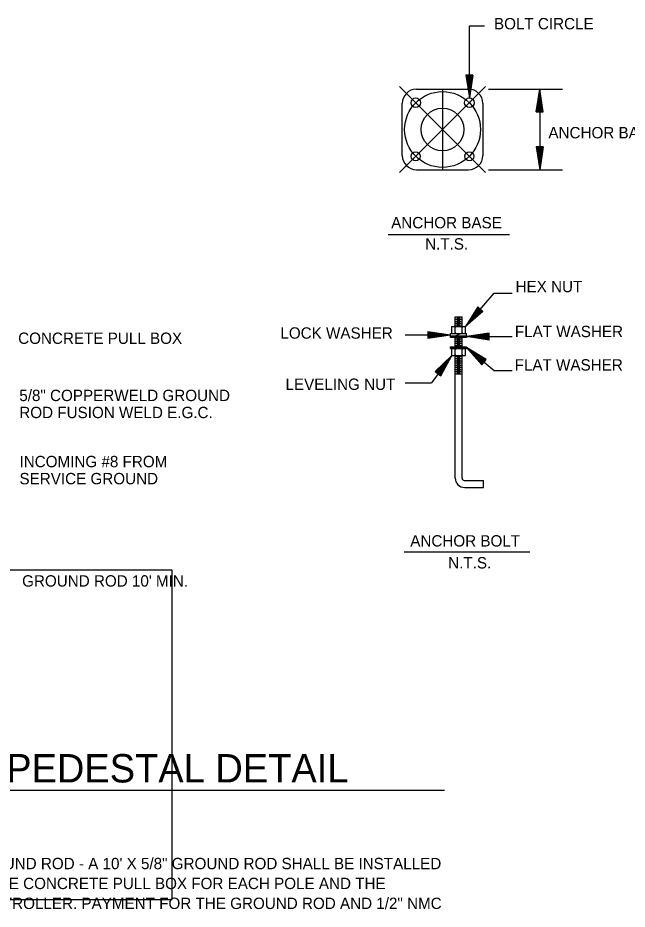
# Model space of a CAD drawing. Extents: x 418532 to 420296, y -565948 to -565286.
# Drawn here: x 419153.1 to 419394.2, y -565645.2 to -565292.4 of the extents above; entities that cross this region are included whole.
import ezdxf

# ---------------------------------------------------------------- set-up
doc = ezdxf.new("R2010")
doc.units = 0
doc.layers.add('R_Draft', color=7, linetype='Continuous')
doc.layers.add('Template', color=7, linetype='Continuous')

msp = doc.modelspace()

# ---------------------------------------------------------------- linework, layer by layer
at = {"layer": 'R_Draft'}
for p, q in [((419331.76, -565324.13), (419331.76, -565295.53)), ((419331.76, -565295.53), (419337.79, -565295.53)), ((419330.41, -565315.13), (419331.76, -565324.13)), ((419333.11, -565315.13), (419330.41, -565315.13)), ((419330.63, -565315.13), (419331.76, -565322.62)), ((419330.86, -565315.13), (419331.76, -565321.07)), ((419331.09, -565315.13), (419331.76, -565319.58)), ((419331.32, -565315.13), (419331.76, -565318.05)), ((419331.55, -565315.13), (419331.76, -565316.55)), ((419333.11, -565315.13), (419331.76, -565324.13)), ((419332.19, -565315.13), (419331.76, -565318.05)), ((419332.65, -565315.13), (419331.76, -565321.07)), ((419332.88, -565315.13), (419331.76, -565322.62)), ((419332.43, -565315.13), (419331.76, -565319.58)), ((419331.97, -565315.13), (419331.76, -565316.55)), ((419338.12, -565353.58), (419304.18, -565319.64)), ((419304.18, -565353.58), (419338.12, -565319.64)), ((419310.84, -565320.67), (419331.46, -565320.67)), ((419321.15, -565320.67), (419321.15, -565352.54)), ((419339.34, -565320.67), (419368.59, -565320.67)), ((419358.24, -565329.67), (419359.59, -565320.67)), ((419358.46, -565329.67), (419359.59, -565322.17)), ((419359.59, -565320.67), (419359.59, -565352.54)), ((419360.94, -565329.67), (419359.59, -565320.67)), ((419360.71, -565329.67), (419359.59, -565322.17)), ((419305.21, -565346.92), (419305.21, -565326.29)), ((419337.09, -565326.29), (419337.09, -565346.92)), ((419358.69, -565329.67), (419359.59, -565323.72)), ((419358.92, -565329.67), (419359.59, -565325.22)), ((419359.15, -565329.67), (419359.59, -565326.74)), ((419360.48, -565329.67), (419359.59, -565323.72)), ((419360.26, -565329.67), (419359.59, -565325.22)), ((419360.03, -565329.67), (419359.59, -565326.74)), ((419358.24, -565329.67), (419360.94, -565329.67)), ((419359.38, -565329.67), (419359.59, -565328.25)), ((419359.8, -565329.67), (419359.59, -565328.25)), ((419358.24, -565343.54), (419359.59, -565352.54)), ((419360.94, -565343.54), (419358.24, -565343.54)), ((419358.46, -565343.54), (419359.59, -565351.04)), ((419358.69, -565343.54), (419359.59, -565349.49)), ((419358.92, -565343.54), (419359.59, -565348)), ((419359.15, -565343.54), (419359.59, -565346.47)), ((419359.38, -565343.54), (419359.59, -565344.97)), ((419360.94, -565343.54), (419359.59, -565352.54)), ((419360.02, -565343.54), (419359.59, -565346.47)), ((419360.48, -565343.54), (419359.59, -565349.49)), ((419360.71, -565343.54), (419359.59, -565351.04)), ((419360.26, -565343.54), (419359.59, -565348)), ((419359.8, -565343.54), (419359.59, -565344.97)), ((419310.84, -565352.54), (419331.46, -565352.54)), ((419339.34, -565352.54), (419368.59, -565352.54)), ((419347.68, -565378.35), (419299.59, -565378.35)), ((419330.21, -565414.57), (419341.63, -565401.41)), ((419341.63, -565401.41), (419348.66, -565401.41)), ((419335.06, -565406.87), (419330.21, -565414.57)), ((419335.23, -565407.02), (419331.19, -565413.43)), ((419335.41, -565407.17), (419332.2, -565412.26)), ((419335.58, -565407.31), (419333.18, -565411.12)), ((419335.75, -565407.46), (419334.18, -565409.97)), ((419336.42, -565408.04), (419334.18, -565409.97)), ((419337.11, -565408.63), (419335.06, -565406.87)), ((419335.93, -565407.61), (419335.16, -565408.83)), ((419336.25, -565407.89), (419335.16, -565408.83)), ((419326.16, -565410.82), (419328.86, -565410.82)), ((419326.16, -565414.57), (419326.16, -565410.82)), ((419326.84, -565411.27), (419328.19, -565411.27)), ((419328.86, -565414.57), (419328.86, -565410.82)), ((419337.11, -565408.63), (419330.21, -565414.57)), ((419336.94, -565408.49), (419331.19, -565413.43)), ((419336.77, -565408.34), (419332.2, -565412.26)), ((419336.59, -565408.19), (419333.18, -565411.12)), ((419324.81, -565417.41), (419324.81, -565414.57)), ((419324.81, -565414.57), (419330.21, -565414.57)), ((419326.16, -565411.68), (419328.86, -565411.68)), ((419326.16, -565412.55), (419328.86, -565412.55)), ((419326.16, -565413.41), (419328.86, -565413.41)), ((419326.16, -565414.28), (419328.86, -565414.28)), ((419326.16, -565417.41), (419326.16, -565414.57)), ((419326.84, -565412.13), (419328.19, -565412.13)), ((419326.84, -565413), (419328.19, -565413)), ((419326.84, -565413.86), (419328.19, -565413.86)), ((419328.86, -565417.41), (419328.86, -565414.57)), ((419330.21, -565417.41), (419330.21, -565414.57)), ((419306.36, -565417.86), (419324.36, -565417.86)), ((419315.36, -565416.51), (419324.36, -565417.86)), ((419315.36, -565416.51), (419315.36, -565419.21)), ((419315.36, -565416.74), (419322.86, -565417.86)), ((419315.36, -565416.97), (419321.31, -565417.86)), ((419315.36, -565417.19), (419319.81, -565417.86)), ((419315.36, -565417.43), (419318.29, -565417.86)), ((419315.36, -565417.65), (419316.78, -565417.86)), ((419315.36, -565419.21), (419324.36, -565417.86)), ((419315.36, -565418.3), (419318.29, -565417.86)), ((419315.36, -565418.76), (419321.31, -565417.86)), ((419315.36, -565418.99), (419322.86, -565417.86)), ((419315.36, -565418.53), (419319.81, -565417.86)), ((419315.36, -565418.07), (419316.78, -565417.86)), ((419324.36, -565418.91), (419324.36, -565417.41)), ((419324.36, -565417.41), (419330.66, -565417.41)), ((419324.36, -565418.31), (419330.66, -565418.31)), ((419324.36, -565418.88), (419324.93, -565418.31)), ((419324.36, -565418.57), (419324.61, -565418.31)), ((419324.65, -565418.91), (419325.25, -565418.31)), ((419324.97, -565418.91), (419325.57, -565418.31)), ((419325.28, -565418.91), (419325.88, -565418.31)), ((419325.6, -565418.91), (419326.2, -565418.31)), ((419325.92, -565418.91), (419326.52, -565418.31)), ((419326.17, -565418.32), (419328.14, -565417.44)), ((419326.24, -565418.91), (419326.84, -565418.31)), ((419326.56, -565418.91), (419327.16, -565418.31)), ((419326.88, -565418.91), (419327.48, -565418.31)), ((419327.19, -565418.91), (419327.79, -565418.31)), ((419327.51, -565418.91), (419328.11, -565418.31)), ((419327.83, -565418.91), (419328.43, -565418.31)), ((419328.15, -565418.91), (419328.75, -565418.31)), ((419328.47, -565418.91), (419329.07, -565418.31)), ((419328.78, -565418.91), (419329.38, -565418.31)), ((419329.1, -565418.91), (419329.7, -565418.31)), ((419329.42, -565418.91), (419330.02, -565418.31)), ((419329.74, -565418.91), (419330.34, -565418.31)), ((419330.06, -565418.91), (419330.66, -565418.31)), ((419330.38, -565418.91), (419330.66, -565418.63)), ((419339.66, -565417.26), (419330.66, -565418.61)), ((419330.66, -565418.91), (419330.66, -565417.41)), ((419330.66, -565418.61), (419348.66, -565418.61)), ((419339.66, -565419.96), (419330.66, -565418.61)), ((419339.66, -565417.49), (419332.16, -565418.61)), ((419339.66, -565419.74), (419332.16, -565418.61)), ((419339.66, -565417.72), (419333.71, -565418.61)), ((419339.66, -565419.51), (419333.71, -565418.61)), ((419339.66, -565417.94), (419335.21, -565418.61)), ((419339.66, -565419.29), (419335.21, -565418.61)), ((419339.66, -565418.17), (419336.74, -565418.61)), ((419339.66, -565419.05), (419336.74, -565418.61)), ((419339.66, -565418.4), (419338.24, -565418.61)), ((419339.66, -565418.83), (419338.24, -565418.61)), ((419339.66, -565419.96), (419339.66, -565417.26)), ((419330.66, -565418.91), (419324.36, -565418.91)), ((419326.16, -565422.66), (419326.16, -565418.91)), ((419326.16, -565419.47), (419328.86, -565419.47)), ((419326.16, -565420.34), (419328.86, -565420.34)), ((419326.16, -565421.2), (419328.86, -565421.2)), ((419326.16, -565422.07), (419328.86, -565422.07)), ((419326.84, -565419.06), (419328.19, -565419.06)), ((419326.84, -565419.92), (419328.19, -565419.92)), ((419326.84, -565420.79), (419328.19, -565420.79)), ((419326.84, -565421.65), (419328.19, -565421.65)), ((419328.86, -565422.66), (419328.86, -565418.91)), ((419324.36, -565423.26), (419324.36, -565422.66)), ((419324.36, -565422.66), (419330.66, -565422.66)), ((419324.36, -565422.97), (419324.66, -565422.66)), ((419324.36, -565423.26), (419330.66, -565423.26)), ((419324.38, -565423.26), (419324.98, -565422.66)), ((419324.7, -565423.26), (419325.3, -565422.66)), ((419324.81, -565426.11), (419324.81, -565423.26)), ((419325.02, -565423.26), (419325.62, -565422.66)), ((419325.34, -565423.26), (419325.94, -565422.66)), ((419325.66, -565423.26), (419326.26, -565422.66)), ((419325.97, -565423.26), (419326.57, -565422.66)), ((419326.16, -565426.11), (419326.16, -565423.26)), ((419326.29, -565423.26), (419326.89, -565422.66)), ((419326.61, -565423.26), (419327.21, -565422.66)), ((419326.84, -565422.52), (419328.19, -565422.52)), ((419326.93, -565423.26), (419327.53, -565422.66)), ((419327.25, -565423.26), (419327.85, -565422.66)), ((419327.56, -565423.26), (419328.16, -565422.66)), ((419327.88, -565423.26), (419328.48, -565422.66)), ((419328.2, -565423.26), (419328.8, -565422.66)), ((419328.52, -565423.26), (419329.12, -565422.66)), ((419328.84, -565423.26), (419329.44, -565422.66)), ((419328.86, -565426.11), (419328.86, -565423.26)), ((419329.16, -565423.26), (419329.76, -565422.66)), ((419329.47, -565423.26), (419330.07, -565422.66)), ((419329.79, -565423.26), (419330.39, -565422.66)), ((419330.11, -565423.26), (419330.66, -565422.71)), ((419330.21, -565426.11), (419330.21, -565423.26)), ((419330.43, -565423.26), (419330.66, -565423.03)), ((419330.66, -565423.26), (419330.66, -565422.66)), ((419330.66, -565422.96), (419341.63, -565432)), ((419336.75, -565429.72), (419330.66, -565422.96)), ((419338.47, -565427.64), (419330.66, -565422.96)), ((419336.9, -565429.55), (419331.82, -565423.92)), ((419338.33, -565427.81), (419331.82, -565423.92)), ((419338.18, -565427.99), (419333.02, -565424.9)), ((419337.04, -565429.37), (419333.02, -565424.9)), ((419324.81, -565426.11), (419316.76, -565436.9)), ((419318.28, -565432.45), (419324.81, -565426.11)), ((419318.46, -565432.59), (419323.9, -565427.3)), ((419318.65, -565432.73), (419322.96, -565428.53)), ((419320.07, -565433.81), (419322.96, -565428.53)), ((419320.25, -565433.95), (419323.9, -565427.3)), ((419320.43, -565434.09), (419324.81, -565426.11)), ((419324.81, -565426.11), (419330.21, -565426.11)), ((419326.16, -565474.57), (419326.16, -565426.11)), ((419326.16, -565426.4), (419328.86, -565426.4)), ((419326.16, -565427.26), (419328.86, -565427.26)), ((419326.16, -565428.13), (419328.86, -565428.13)), ((419326.16, -565428.99), (419328.86, -565428.99)), ((419326.84, -565426.85), (419328.19, -565426.85)), ((419326.84, -565427.71), (419328.19, -565427.71)), ((419326.84, -565428.58), (419328.19, -565428.58)), ((419328.86, -565474.61), (419328.86, -565426.11)), ((419337.19, -565429.2), (419334.17, -565425.85)), ((419338.04, -565428.16), (419334.17, -565425.85)), ((419337.89, -565428.34), (419335.35, -565426.82)), ((419337.33, -565429.02), (419335.35, -565426.82)), ((419337.75, -565428.52), (419336.51, -565427.78)), ((419337.48, -565428.84), (419336.51, -565427.78)), ((419336.75, -565429.72), (419338.47, -565427.64)), ((419318.28, -565432.45), (419320.43, -565434.09)), ((419318.82, -565432.86), (419322.05, -565429.73)), ((419319.01, -565433), (419321.13, -565430.94)), ((419319.19, -565433.14), (419320.22, -565432.14)), ((419319.53, -565433.4), (419320.22, -565432.14)), ((419319.71, -565433.53), (419321.13, -565430.94)), ((419319.89, -565433.67), (419322.05, -565429.73)), ((419326.16, -565429.86), (419328.86, -565429.86)), ((419326.16, -565430.72), (419328.86, -565430.72)), ((419326.16, -565431.59), (419328.86, -565431.59)), ((419326.16, -565432.45), (419328.86, -565432.45)), ((419326.84, -565429.44), (419328.19, -565429.44)), ((419326.84, -565430.31), (419328.19, -565430.31)), ((419326.84, -565431.17), (419328.19, -565431.17)), ((419326.84, -565432.04), (419328.19, -565432.04)), ((419341.63, -565432), (419348.66, -565432)), ((419326.16, -565433.32), (419328.86, -565433.32)), ((419326.84, -565432.9), (419328.19, -565432.9)), ((419306.36, -565436.9), (419316.76, -565436.9)), ((419329.76, -565475.51), (419337.41, -565475.51)), ((419329.91, -565478.32), (419337.41, -565478.32)), ((419337.41, -565478.32), (419337.41, -565475.51)), ((419355.73, -565503.91), (419306, -565503.91)), ((418930.96, -565598.08), (419321.99, -565598.08))]:
    msp.add_line(p, q, dxfattribs=at)
for centre, radius in [((419321.15, -565336.61), 15), ((419310.54, -565326), 1.87), ((419331.76, -565326), 1.87), ((419321.15, -565336.61), 8.44), ((419310.54, -565347.21), 1.8), ((419331.76, -565347.21), 1.8)]:
    msp.add_circle(centre, radius, dxfattribs=at)
for centre, radius, start, end in [((419310.84, -565326.29), 5.62, 90, 180), ((419331.46, -565326.29), 5.62, 360, 90), ((419310.84, -565346.92), 5.62, 180, 270), ((419331.46, -565346.92), 5.62, 270, 0), ((419325.71, -565415.02), 0.45, 0, 90), ((419326.61, -565415.02), 0.45, 90, 180), ((419328.41, -565415.02), 0.45, 0, 90), ((419329.31, -565415.02), 0.45, 90, 180), ((419325.71, -565416.96), 0.45, 270, 0), ((419326.61, -565416.96), 0.45, 180, 270), ((419328.41, -565416.96), 0.45, 270, 0), ((419329.31, -565416.96), 0.45, 180, 270), ((419325.71, -565423.71), 0.45, 0, 90), ((419325.71, -565425.66), 0.45, 270, 0), ((419326.61, -565423.71), 0.45, 90, 180), ((419326.61, -565425.66), 0.45, 180, 270), ((419328.41, -565423.71), 0.45, 0, 90), ((419328.41, -565425.66), 0.45, 270, 0), ((419329.31, -565423.71), 0.45, 90, 180), ((419329.31, -565425.66), 0.45, 180, 270), ((419329.91, -565474.57), 3.75, 180, 270), ((419329.76, -565474.61), 0.9, 180, 270)]:
    msp.add_arc(centre, radius, start, end, dxfattribs=at)
at = {"layer": 'Template'}
msp.add_lwpolyline([(419214.2, -565511.02), (418906.32, -565511.02), (418906.32, -565641.34), (419214.2, -565641.34)], close=True, dxfattribs=at)

# ---------------------------------------------------------------- texts
at = {"layer": 'R_Draft'}
for s, height, p in [('BOLT CIRCLE', 4.5, (419341.5, -565296.98)), ('ANCHOR BASE SQUARE', 4.5, (419363.05, -565340.13)), ('ANCHOR BASE', 4.5, (419300.82, -565375.74)), ('N.T.S.', 4.5, (419314.25, -565384.14)), ('HEX NUT', 4.5, (419350.05, -565401.02)), ('LOCK WASHER', 4.5, (419256.99, -565419.42)), ('FLAT WASHER', 4.5, (419349.78, -565418.81)), ('CONCRETE PULL BOX', 4.5, (419153.22, -565421.49)), ('FLAT WASHER', 4.5, (419349.69, -565432.04)), ('LEVELING NUT', 4.5, (419259.01, -565439.7)), ('5/8" COPPERWELD GROUND ', 4.5, (419153.66, -565444.12)), ('ROD FUSION WELD E.G.C.', 4.5, (419153.66, -565450.87)), ('INCOMING #8 FROM ', 4.5, (419153.74, -565470.3)), ('SERVICE GROUND', 4.5, (419153.74, -565477.05)), ('ANCHOR BOLT', 4.5, (419308.38, -565501.69)), ('N.T.S.', 4.5, (419323.39, -565510.37)), ("GROUND ROD 10' MIN.", 4.5, (419154.78, -565517.55)), ('PEDESTRIAN PUSH BUTTON PEDESTAL DETAIL', 11.25, (418936.17, -565595.07)), ('GROUND ROD - A 10\' X 5/8" GROUND ROD SHALL BE INSTALLED ', 4.5, (419133.79, -565629.41)), ('IN THE CONCRETE PULL BOX FOR EACH POLE AND THE ', 4.5, (419133.79, -565637.28)), ('CONTROLLER. PAYMENT FOR THE GROUND ROD AND 1/2" NMC ', 4.5, (419133.79, -565645.16))]:
    msp.add_text(s, height=height, dxfattribs=at).set_placement(p)

doc.saveas('drawing.dxf')
